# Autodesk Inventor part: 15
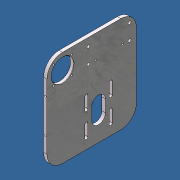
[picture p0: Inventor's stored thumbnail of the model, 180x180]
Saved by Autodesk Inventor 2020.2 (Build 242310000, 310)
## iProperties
Created: 2016-09
Part Number: 15
Material: Aluminum 6061
Document SubType Name: Modeling
Designer: Mike Taylor
Mass: 1718.02 g
Surface Area: 1478.5 cm^2
Volume: 636.305 cm^3
Density: 2.7 g/cm^3
Appearance: Aluminum - Flat
Translation Standard: STEP AP214IS
FileName: 29_5060_0_1.stp
PreProcessor: ACIS
PostProcessor: Build: 160, Release: 2012 RTM - Date: Tue 03/01/2011
Sent Units: centimeter
Uncertainty: 0.0
Author: Mike Taylor
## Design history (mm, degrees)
node "151"
node "15"
node "Base1"
